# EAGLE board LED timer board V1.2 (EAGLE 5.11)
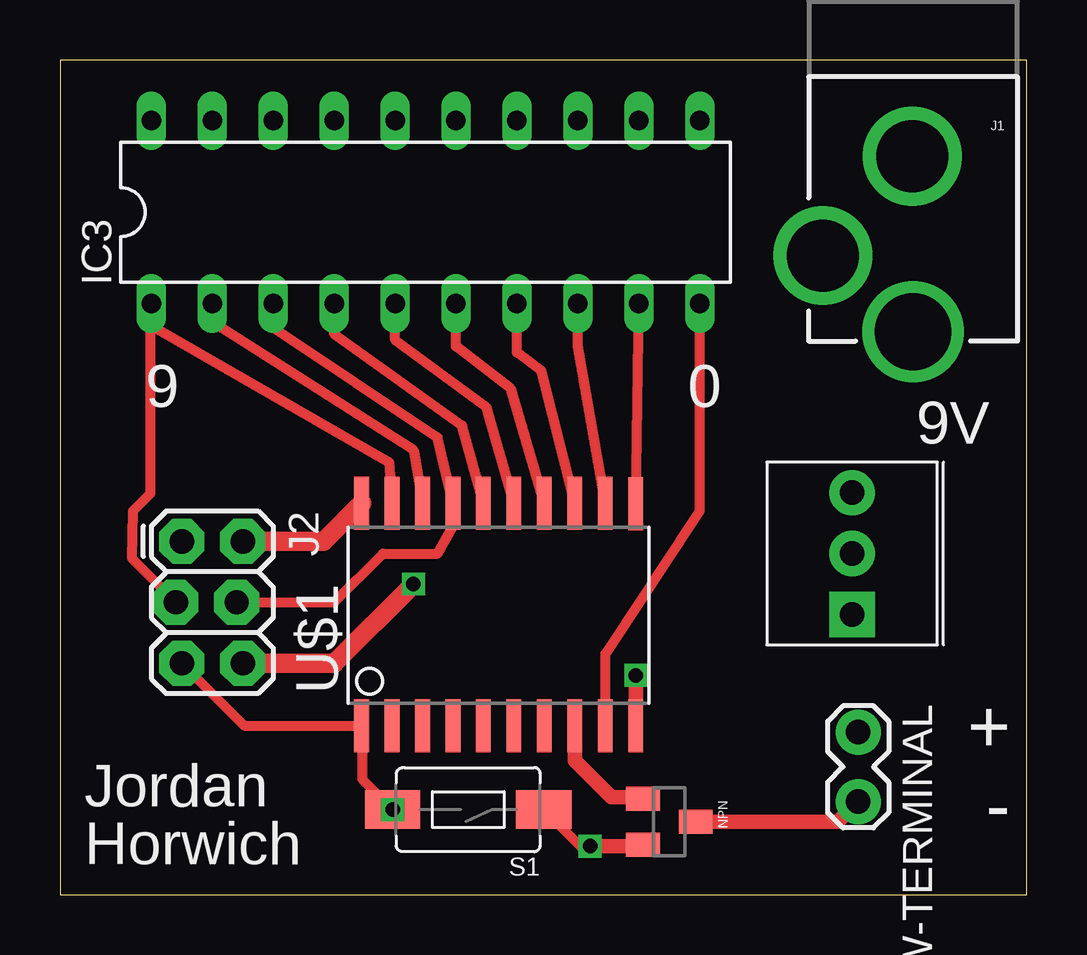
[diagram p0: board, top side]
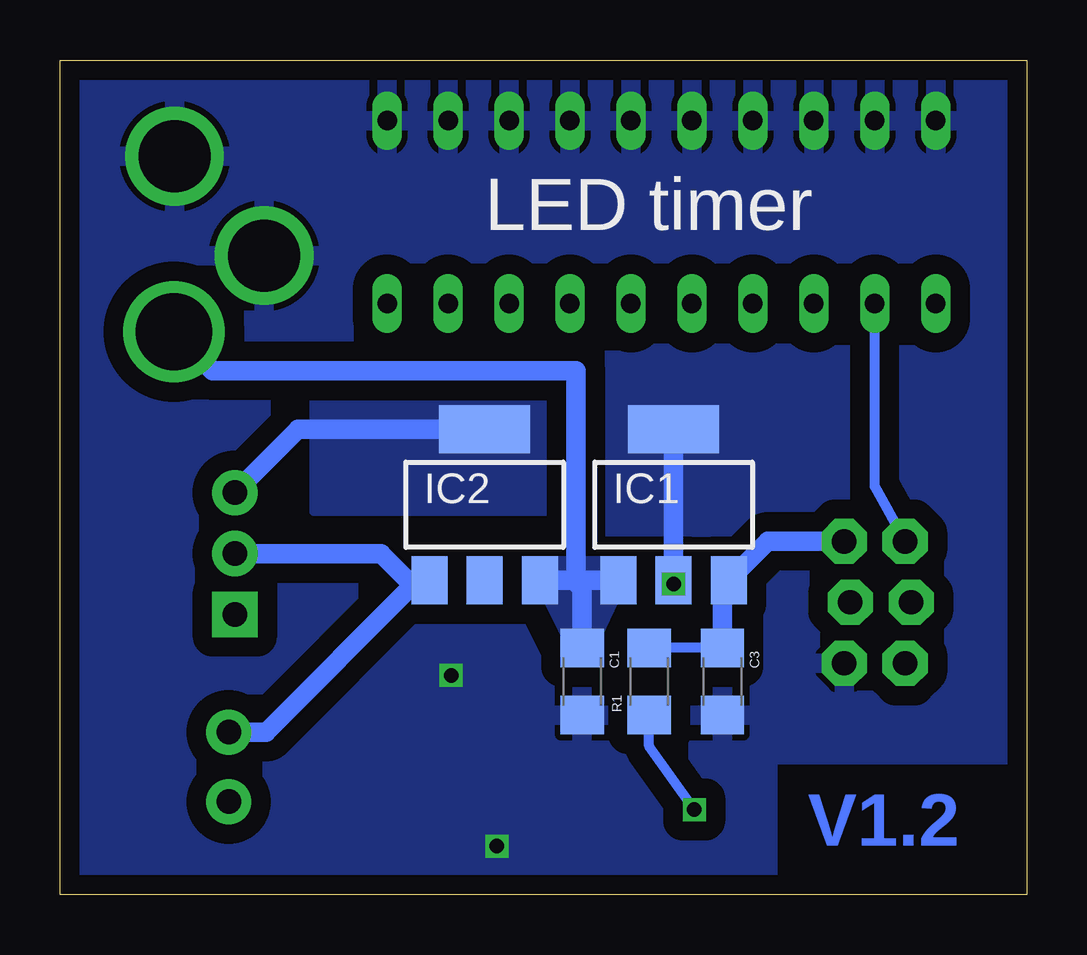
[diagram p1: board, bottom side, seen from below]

Size 40.31 x 34.79 mm. Coordinates in mm from the lower left corner, seen from the top.
Outline: 0,0 40.31,0 40.31,34.79 0,34.79 0,0
Copper layers (1*16): Top 0.0356mm / dielectric 1.5011mm / Bottom 0.0356mm
Design rules "LaenPCBOrder": minimum track width 6mil, minimum drill 13mil, track to track 6mil, track to pad 6mil, pad to pad 6mil, via to via 6mil, smd to smd 6mil, copper to edge 15mil, drill to drill 6mil, minimum pad ring 7mil, minimum via ring 7mil, stop-mask expansion 4mil, vias tented up to drill 0mil, thermal gap 10mil

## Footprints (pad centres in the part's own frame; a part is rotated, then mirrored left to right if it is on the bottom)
1206 = smd 1.6 x 1.8: 1 -1.4,0; 2 1.4,0
SOT223 = smd 1.5 x 2: 1 -2.3,-3.15; 2 0,-3.15; 3 2.3,-3.15 | smd 3.8 x 2: 4 0,3.15
DIL20 = drill 0.813 long: 1 -11.43,-3.81; 2 -8.89,-3.81; 3 -6.35,-3.81; 4 -3.81,-3.81; 5 -1.27,-3.81; 6 1.27,-3.81; 7 3.81,-3.81; 8 6.35,-3.81; 9 8.89,-3.81; 10 11.43,-3.81; 11 11.43,3.81; 12 8.89,3.81; 13 6.35,3.81; 14 3.81,3.81; 15 1.27,3.81; 16 -1.27,3.81; 17 -3.81,3.81; 18 -6.35,3.81; 19 -8.89,3.81; 20 -11.43,3.81
POWER_JACK_PTH_LOCK = drill 2.997 pad 4.115 round: GND 0.025,6.557; GNDBREAK 3.762,10.7 | drill 3.2 pad 4.115 round: PWR 0,13.878
2X3_LOCK = drill 1.016 pad 1.88 octagon: 1 0,0; 2 0,2.54; 3 2.54,-0.254; 4 2.54,2.286; 5 5.08,0; 6 5.08,2.54
SOT23 = smd 1 x 1.4: 1 -0.95,-1.1; 2 0.95,-1.1; 3 0,1.1
TACTILE-SWITCH-1101NE = smd 2.3 x 1.6: P$1 -3.15,0; P$2 3.15,0
1X02_LOCK = drill 1.016 pad 1.88 round: 1 -0.178,0; 2 2.718,0
SO20L$ = smd 0.61 x 2.21: 1 -5.715,-4.636; 2 -4.445,-4.636; 3 -3.175,-4.636; 4 -1.905,-4.636; 5 -0.635,-4.636; 6 0.635,-4.636; 7 1.905,-4.636; 8 3.175,-4.636; 9 4.445,-4.636; 10 5.715,-4.636; 11 5.715,4.61; 12 4.445,4.636; 13 3.175,4.636; 14 1.905,4.636; 15 0.635,4.636; 16 -0.635,4.636; 17 -1.905,4.636; 18 -3.175,4.636; 19 -4.445,4.636; 20 -5.715,4.636
3362U = drill 1.016 pad 1.88 square: P$1 0,2.54 | drill 1.016 pad 1.88 round: P$2 2.54,2.54; P$3 5.08,2.54

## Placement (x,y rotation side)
C1  0.33uF  [1206]  18.54,8.89 270 bottom
C3  0.1uF  [1206]  12.7,8.89 270 bottom
IC1  7805, ADJ = OUT  [SOT223]  14.73,16.26 0 bottom
IC2  LM317L  [SOT223]  22.61,16.26 0 bottom
IC3  DIP switch  [DIL20]  15.24,28.45 0 top
J1  POWER_JACKPTH_LOCK  [POWER_JACK_PTH_LOCK]  35.56,37.34 180 top
J2  AVR_SPI_PRG_62X3_LOCK  [2X3_LOCK]  5.08,14.73 270 top
NPN  2N3904  [SOT23]  25.4,3.05 270 top
R1  10K  [1206]  15.75,8.89 90 bottom
S1  SWITCH-MOMENTARY-2-SMD-1101NE  [TACTILE-SWITCH-1101NE]  17.02,3.56 180 top
SCREW-TERMINAL  LED  [1X02_LOCK]  33.27,6.6 270 top
U$1  TINY2313-*S*  [SO20L$]  18.29,11.68 0 top
U$3  1K  [3362U]  35.56,11.68 90 top

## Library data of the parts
C1 C3 J1 J2 NPN R1 S1 SCREW-TERMINAL U$3 = SparkFun
IC1 IC2 = v-reg
IC3 = ic-package
U$1 = avr-6

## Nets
9V: C1.1 IC1.1 IC2.3 J1.PWR
GND: C1.2 C3.2 IC1.4 IC3.11 IC3.12 IC3.13 IC3.14 IC3.15 IC3.16 IC3.17 IC3.18 IC3.19 IC3.20 J1.GND J1.GNDBREAK J2.6 NPN.2 S1.P$1 U$1.10
MISO: IC3.2 J2.1 U$1.18
MOSI: IC3.3 J2.4 U$1.17
N$1: IC2.4 U$3.P$3
N$2: IC2.1 SCREW-TERMINAL.1 U$3.P$2
N$4: NPN.3 SCREW-TERMINAL.2
PB0: IC3.8 U$1.12
PB1: IC3.7 U$1.13
PB2: IC3.6 U$1.14
PB3: IC3.5 U$1.15
PB4: IC3.4 U$1.16
PD4: NPN.1 U$1.8
PD5: IC3.10 U$1.9
PD6: IC3.9 U$1.11
RESET: J2.5 R1.1 S1.P$2 U$1.1
SCK: IC3.1 J2.3 U$1.19
VCC: C3.1 IC1.3 J2.2 R1.2 U$1.20

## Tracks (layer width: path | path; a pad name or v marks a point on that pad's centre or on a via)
9V
  Bottom 0.813: J1.PWR 33.94,21.84 18.8,21.84 18.8,13.21 18.9,13.11 | 18.9,13.11 IC2.3 | 18.9,13.11 IC1.1 | 18.9,13.11 18.54,12.75 C1.1
  pour Bottom (isolate 0.813, rank 2, no thermals): 16.76,13.72 20.45,13.72 18.54,9.91
GND  (via drill 0.6)
  Top 0.406: 24.23,2.03 NPN.2 | v22.1,2.03 21.69,2.03 S1.P$1
  Top 0.61: U$1.10 v24,9.14 | v22.1,2.03 24.23,2.03
  Top 0.813: v14.73,12.95 11.43,9.65 J2.6
  Bottom 0.813: v14.73,12.95 IC1.4
  pour Bottom (isolate 0.813, no thermals): 17.27,17.27 8.38,17.27 8.38,21.08 17.27,21.08
  pour Bottom (isolate 0.813, rank 3): 0,34.8 40.26,34.8 40.26,0 10.79,0 10.79,5.84 0,5.84
MISO
  Top 0.406: U$1.18 14.73,18.54 6.35,23.88 IC3.2
  Bottom 0.406: J2.1 6.35,17.02 IC3.2
MOSI
  Top 0.406: IC3.3 8.89,23.62 15.75,19.05 U$1.17 16.38,15.37 15.75,14.22 13.46,14.22 11.43,12.19 J2.4
N$1
  Bottom 0.813: U$3.P$3 30.38,19.41 IC2.4
  pour Bottom (isolate 0.813, no thermals): 19.81,20.83 29.72,20.83 29.72,16 19.81,16
N$2
  Bottom 0.61: IC2.1 25.4,13.11 25.6,12.9
  Bottom 0.813: U$3.P$2 26.92,14.22 25.6,12.9 31.72,6.78 SCREW-TERMINAL.1
N$4
  Top 0.61: NPN.3 32.44,3.05 SCREW-TERMINAL.2
PB0
  Top 0.406: U$1.12 21.59,22.86 IC3.8
PB1
  Top 0.406: U$1.13 20.07,21.84 19.05,22.61 IC3.7
PB2
  Top 0.406: U$1.14 18.8,21.08 16.51,22.86 IC3.6
PB3
  Top 0.406: U$1.15 17.78,20.32 13.97,23.11 IC3.5
PB4
  Top 0.406: U$1.16 16.76,19.56 11.43,23.37 IC3.4
PD4
  Top 0.61: U$1.8 21.46,5.59 22.99,4.06 24.23,4.06 NPN.1
PD5
  Top 0.406: U$1.9 22.73,10.03 26.67,16 IC3.10
PD6
  Top 0.406: U$1.11 IC3.9
RESET  (via drill 0.6)
  Top 0.406: J2.5 7.68,7.05 U$1.1 12.6,7.02 12.6,4.83 S1.P$2
  Bottom 0.406: R1.1 15.75,6.2 S1.P$2
  other vias: 13.87,3.56
SCK
  Top 0.406: U$1.19 13.72,18.03 3.78,23.75 | 3.78,23.75 3.81,23.88 IC3.1 | J2.3 3.02,14 3.05,16 3.78,16.73 3.78,23.75
VCC
  Top 0.813: U$1.20 10.99,14.73 J2.2
  Bottom 0.406: C3.1 R1.2
  Bottom 0.813: J2.2 10.81,14.73 IC1.3 12.7,12.84 C3.1

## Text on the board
Bottom: V1.2
tPlace: 9 | 0 | 9V | + | - | Jordan | Horwich
bPlace: LED timer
